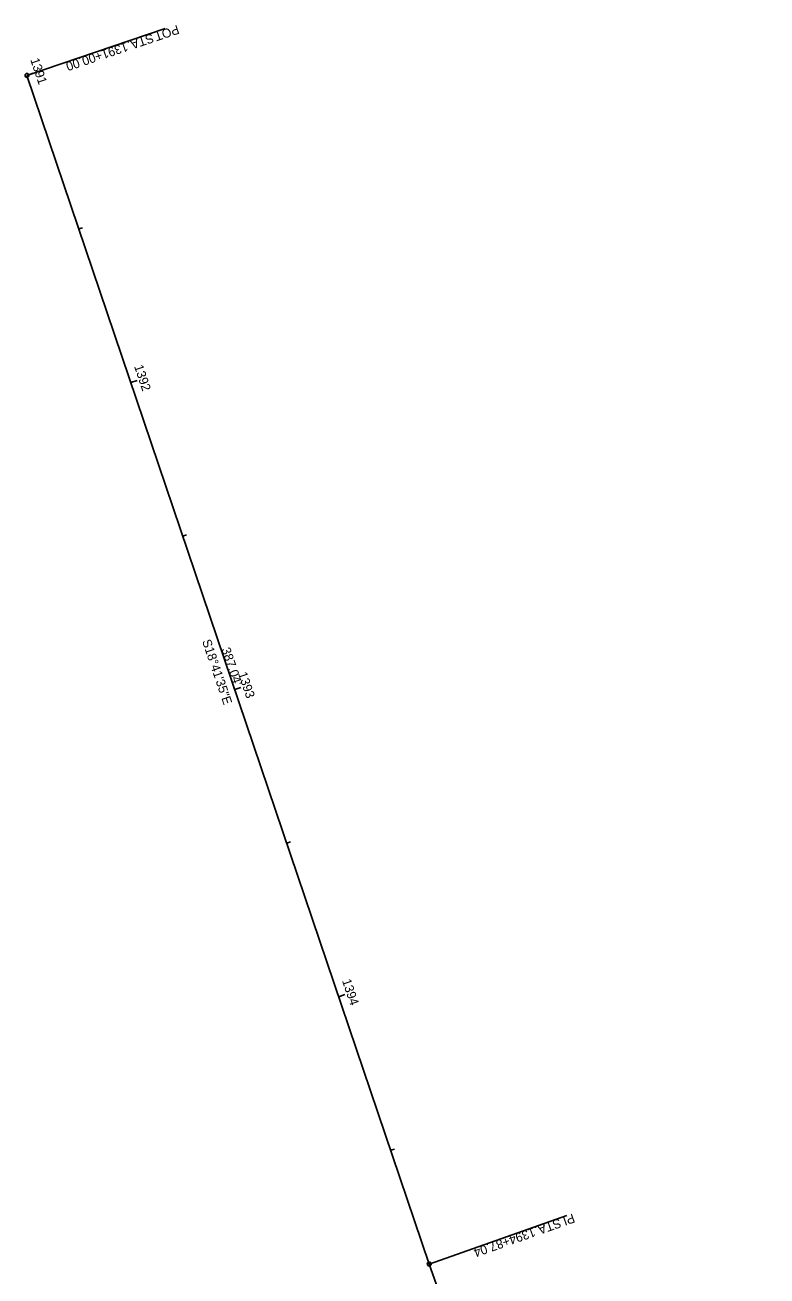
# Model space of a CAD drawing. Extents: x 208719 to 209081, y 284970 to 285717.
# Drawn here: x 208718.9 to 208947.7, y 285330.9 to 285716.7 of the extents above; entities that cross this region are included whole.
import ezdxf

# ---------------------------------------------------------------- set-up
doc = ezdxf.new("R2010")
doc.units = 0
for name, color, linetype in [('GE_P_Alignment', 7, 'Continuous'), ('GE_P_Alignment_100_Bearings', 7, 'Continuous'), ('GE_P_Alignment_100_Curve_Data', 7, 'Continuous'), ('GE_P_Alignment_100_Distances', 7, 'Continuous'), ('SC_Scratch1', 7, 'Continuous'), ('SC_Scratch2', 7, 'Continuous')]:
    doc.layers.add(name, color=color, linetype=linetype)

msp = doc.modelspace()

# ---------------------------------------------------------------- linework, layer by layer
at = {"layer": 'GE_P_Alignment'}
for p, q in [((208719.46, 285701.2), (208843.51, 285334.58)), ((208843.51, 285334.58), (208880.59, 285229.56))]:
    msp.add_line(p, q, dxfattribs=at)
at = {"layer": 'GE_P_Alignment_100_Bearings'}
for p, q in [((208719.46, 285701.2), (208762.09, 285715.63)), ((208843.51, 285334.58), (208885.94, 285349.56))]:
    msp.add_line(p, q, dxfattribs=at)
for centre in [(208719.46, 285701.2), (208843.51, 285334.58)]:
    msp.add_circle(centre, 0.6, dxfattribs=at)
at = {"layer": 'GE_P_Alignment_100_Distances'}
for p, q in [((208719.46, 285701.2), (208721.36, 285701.85)), ((208735.49, 285653.84), (208736.63, 285654.23)), ((208751.51, 285606.48), (208753.41, 285607.12)), ((208767.54, 285559.12), (208768.68, 285559.5)), ((208783.56, 285511.75), (208785.46, 285512.4)), ((208799.59, 285464.39), (208800.73, 285464.78)), ((208815.61, 285417.03), (208817.51, 285417.67)), ((208831.64, 285369.67), (208832.78, 285370.05))]:
    msp.add_line(p, q, dxfattribs=at)
at = {"layer": 'SC_Scratch1'}
for q in [(208719.46, 285701.2), (208947.67, 285039.59)]:
    msp.add_line((208843.51, 285334.58), q, dxfattribs=at)

# ---------------------------------------------------------------- texts
at = {"layer": 'GE_P_Alignment_100_Bearings'}
for s, rotation, p in [('POT', 198.6931, (208765.81, 285716.84)), ('1391+00.00', 198.6931, (208750.04, 285711.51)), (' STA. ', 198.6931, (208758.99, 285714.53)), (' STA. ', 199.4477, (208884.58, 285349.04)), ('PI', 199.4477, (208887.78, 285350.17)), ('1394+87.04', 199.4477, (208875.67, 285345.89))]:
    msp.add_text(s, height=2.8, rotation=rotation, dxfattribs=at).set_placement(p)
at = {"layer": 'GE_P_Alignment_100_Curve_Data'}
msp.add_text("387.04'", height=2.8, rotation=288.6931, dxfattribs=at).set_placement((208779.39, 285524.23))
at = {"layer": 'GE_P_Alignment_100_Distances'}
for s, p in [('1391', (208720.46, 285706.05)), ('1392', (208752.47, 285611.45)), ('1393', (208784.53, 285516.71)), ('1394', (208816.58, 285421.99))]:
    msp.add_text(s, height=2.8, rotation=288.6931, dxfattribs=at).set_placement(p)
at = {"layer": 'SC_Scratch2'}
msp.add_text('S18°41\'35"E', height=2.8, rotation=288.6931, dxfattribs=at).set_placement((208773.43, 285526.72))

doc.saveas('drawing.dxf')
